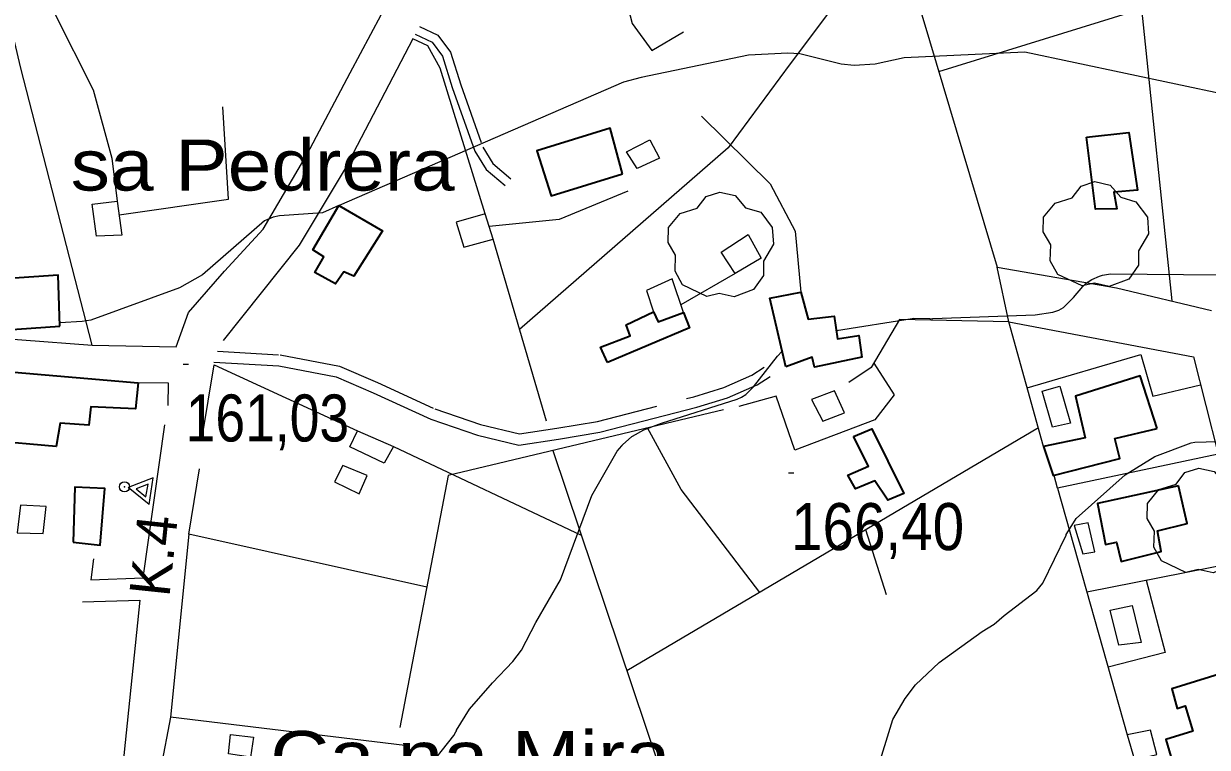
# Model space of a CAD drawing. Extents: x 480269 to 484877, y 4383588 to 4386804.
# Drawn here: x 481183 to 481403.4, y 4385293.4 to 4385428.1 of the extents above; entities that cross this region are included whole.
import ezdxf
from ezdxf.enums import TextEntityAlignment as Align

# ---------------------------------------------------------------- set-up
doc = ezdxf.new("R2010")
doc.units = 0
doc.header["$LTSCALE"] = 3.8
doc.header["$PDMODE"] = 32
doc.header["$PDSIZE"] = 1.9
doc.linetypes.add('MEDIUM_DASHED', pattern=[4.5, 3, -1.5])
for name, color, linetype, lineweight in [('21', 7, 'Continuous', 25), ('29', 7, 'Continuous', 13), ('38', 7, 'Continuous', 25), ('41', 7, 'Continuous', 13), ('47', 7, 'Continuous', 35), ('51', 7, 'Continuous', 13), ('7', 7, 'Continuous', 13), ('9', 7, 'Continuous', 13)]:
    doc.layers.add(name, color=color, linetype=linetype, lineweight=lineweight)
doc.layers.add('5', color=7, linetype='Continuous')

msp = doc.modelspace()

# ---------------------------------------------------------------- linework, layer by layer
at = {"layer": '21'}
for points in [[(481377.88, 4385353.76), (481374.54, 4385353.01), (481372.59, 4385359.75), (481375.89, 4385360.67)], [(481380.16, 4385329.43), (481382.42, 4385329.81), (481381.2, 4385335.22), (481378.6, 4385334.74)], [(481391.04, 4385312.94), (481386.91, 4385312.47), (481385.3, 4385318.98), (481389.36, 4385319.83)]]:
    msp.add_lwpolyline(points, close=True, dxfattribs=at)
at = {"layer": '29'}
for points in [[(481310.22, 4385377.38), (481305.68, 4385379.5), (481304.27, 4385382.04), (481304.37, 4385385.02), (481303, 4385387.43), (481303.04, 4385390.18), (481305.2, 4385392.78), (481308.39, 4385393.78), (481310.04, 4385395.97), (481312.61, 4385396.8), (481315.47, 4385396.15), (481317.42, 4385393.88), (481320.23, 4385393.06), (481322.36, 4385390.21), (481322.6, 4385387.08), (481320.72, 4385383.93), (481320.72, 4385381.25), (481318.9, 4385378.64), (481315.28, 4385377.3), (481312.51, 4385377.93)], [(481380.05, 4385379.31), (481375.51, 4385381.43), (481374.1, 4385383.97), (481374.2, 4385386.95), (481372.83, 4385389.36), (481372.87, 4385392.11), (481375.03, 4385394.71), (481378.22, 4385395.71), (481379.87, 4385397.9), (481382.44, 4385398.73), (481385.3, 4385398.08), (481387.25, 4385395.81), (481390.06, 4385394.99), (481392.19, 4385392.14), (481392.43, 4385389.01), (481390.55, 4385385.86), (481390.55, 4385383.18), (481388.73, 4385380.57), (481385.11, 4385379.23), (481382.34, 4385379.86)], [(481399.37, 4385326), (481394.83, 4385328.12), (481393.42, 4385330.66), (481393.52, 4385333.64), (481392.15, 4385336.05), (481392.19, 4385338.8), (481394.35, 4385341.4), (481397.54, 4385342.4), (481399.19, 4385344.59), (481401.76, 4385345.42), (481404.62, 4385344.77), (481406.57, 4385342.5), (481409.38, 4385341.68), (481411.51, 4385338.83), (481411.75, 4385335.7), (481409.87, 4385332.55), (481409.87, 4385329.87), (481408.05, 4385327.26), (481404.43, 4385325.92), (481401.66, 4385326.55)]]:
    msp.add_lwpolyline(points, close=True, dxfattribs=at)
at = {"layer": '38', "linetype": 'MEDIUM_DASHED'}
for points in [[(481256.73, 4385427.61), (481260.15, 4385425.99), (481262.46, 4385422.83), (481264.39, 4385416.78), (481268.47, 4385405.16), (481270.39, 4385402.09), (481273.74, 4385399.24)], [(481219.11, 4385367.17), (481230.76, 4385366.48), (481241.8, 4385364.36), (481248.89, 4385361.31), (481259.57, 4385356.44), (481268.08, 4385353.52), (481275.31, 4385351.78), (481282.26, 4385352.82), (481289.86, 4385354.08), (481307.8, 4385358.69), (481313.33, 4385360.42), (481318.6, 4385362.69), (481320.88, 4385364.17)]]:
    msp.add_lwpolyline(points, dxfattribs=at)
at = {"layer": '38'}
for points in [[(481255.9, 4385426.18), (481259.07, 4385424.68), (481260.97, 4385422.07), (481262.82, 4385416.26), (481266.98, 4385404.43), (481269.13, 4385401), (481272.68, 4385397.99)], [(481218.45, 4385365.15), (481230.51, 4385364.45), (481241.19, 4385362.39), (481248.06, 4385359.43), (481258.81, 4385354.54), (481267.51, 4385351.55), (481275.22, 4385349.69), (481282.58, 4385350.8), (481290.28, 4385352.08), (481308.36, 4385356.72), (481314.04, 4385358.5), (481319.56, 4385360.88), (481321.99, 4385362.45)]]:
    msp.add_lwpolyline(points, dxfattribs=at)
at = {"layer": '41'}
for p, q in [((481207.13, 4385343.61), (481202.46, 4385341.81)), ((481206.36, 4385338.66), (481202.46, 4385341.81)), ((481206.36, 4385338.66), (481207.13, 4385343.61))]:
    msp.add_line(p, q, dxfattribs=at)
msp.add_lwpolyline([(481203.96, 4385341.56), (481205.8, 4385340.05), (481206.19, 4385342.4)], close=True, dxfattribs=at)
msp.add_point((481201.8, 4385341.91), dxfattribs=at)
at = {"layer": '47'}
for points in [[(481294.52, 4385400.18), (481292.21, 4385408.7), (481278.57, 4385404.44), (481281.2, 4385396.08)], [(481380.89, 4385407.02), (481388.72, 4385407.87), (481390.38, 4385397.16), (481385.97, 4385396.77), (481386.52, 4385393.67), (481382.57, 4385393.58)], [(481241.71, 4385394.3), (481249.84, 4385389.56), (481244.49, 4385381.11), (481242.64, 4385381.94), (481241.06, 4385379.68), (481237.22, 4385381.84), (481238.89, 4385384.75), (481236.88, 4385386.04)], [(481189.78, 4385371.83), (481189.43, 4385381.29), (481168.55, 4385379.92), (481169.2, 4385370.38)], [(481324.89, 4385364.24), (481321.89, 4385377.06), (481327.71, 4385378.13), (481329.07, 4385373.1), (481333.92, 4385373.67), (481334.52, 4385369.45), (481338.49, 4385370.09), (481339.04, 4385366.07), (481330.25, 4385364.19), (481329.77, 4385366.07)], [(481291.7, 4385365.07), (481290.39, 4385367.92), (481295.91, 4385370.01), (481295.18, 4385372.08), (481300.27, 4385374.47), (481301.12, 4385372.66), (481305.86, 4385374.38), (481306.99, 4385371.5)], [(481204.32, 4385361.26), (481203.82, 4385356.45), (481195.53, 4385356.79), (481195.15, 4385353.4), (481189.8, 4385353.78), (481189.05, 4385349.42), (481176.39, 4385350.53), (481177.62, 4385363.6)], [(481394.04, 4385352.76), (481390.85, 4385362.56), (481378.81, 4385358.78), (481380.6, 4385351.05), (481372.87, 4385349.44), (481374.68, 4385344.01), (481387.06, 4385347.21), (481386.14, 4385350.92)], [(481337.48, 4385351.27), (481340.92, 4385352.7), (481346.84, 4385340.69), (481343.9, 4385339.44), (481341.44, 4385343.01), (481337.86, 4385341.53), (481336.47, 4385344.09), (481340.27, 4385345.77)], [(481192.24, 4385331.61), (481197.25, 4385331.09), (481198.12, 4385341.58), (481192.58, 4385341.87)], [(481397.99, 4385342.08), (481382.91, 4385338.83), (481384.39, 4385331.17), (481386.43, 4385331.65), (481387.3, 4385328.05), (481394.76, 4385329.86), (481394.06, 4385333.76), (481399.61, 4385335.09)], [(481417.41, 4385294.85), (481414.29, 4385305.44), (481409.84, 4385304.29), (481408.17, 4385307.83), (481396.78, 4385304.34), (481397.74, 4385300.68), (481399.21, 4385301.15), (481400.67, 4385296.45), (481395.64, 4385294.9), (481397.2, 4385289.59)]]:
    msp.add_lwpolyline(points, close=True, dxfattribs=at)
at = {"layer": '47', "lineweight": 13}
for points in [[(481297.22, 4385401.16), (481295.25, 4385404.27), (481299.61, 4385406.51), (481301.4, 4385403.07)], [(481201.32, 4385388.78), (481196.61, 4385388.58), (481195.8, 4385394.56), (481200.42, 4385395.07)], [(481270.42, 4385388), (481268.93, 4385392.72), (481263.52, 4385391.2), (481264.95, 4385386.52)], [(481320.28, 4385384.48), (481315.44, 4385381.66), (481312.86, 4385385.62), (481317.89, 4385388.89)], [(481331.79, 4385354.17), (481335.81, 4385355.72), (481333.97, 4385359.8), (481329.7, 4385358.2)], [(481251.89, 4385349.42), (481250.15, 4385346.33), (481243.74, 4385349.36), (481245.15, 4385352.35)], [(481245.51, 4385340.64), (481246.98, 4385344.05), (481242.44, 4385345.89), (481240.87, 4385342.83)], [(481186.67, 4385333.21), (481187.23, 4385338.26), (481182.47, 4385338.5), (481181.82, 4385333.38)], [(481225.26, 4385291.59), (481221.14, 4385292.24), (481221.5, 4385295.8), (481225.83, 4385295.35)], [(481393.96, 4385292.11), (481392.79, 4385296.62), (481388.43, 4385295.78), (481389.78, 4385291.08)]]:
    msp.add_lwpolyline(points, close=True, dxfattribs=at)
at = {"layer": '51'}
for p, q in [((481391.1, 4385430.92), (481396.74, 4385376.54)), ((481280.33, 4385354.17), (481270.42, 4385388)), ((481315.44, 4385381.66), (481305.38, 4385375.81)), ((481366.41, 4385372.62), (481364.24, 4385382.84)), ((481371.91, 4385352.93), (481295.3, 4385307.64)), ((481251.89, 4385349.42), (481286.82, 4385332.9)), ((481375.47, 4385341.67), (481388.43, 4385295.78)), ((481213.8, 4385333.13), (481210.37, 4385299.06)), ((481343.65, 4385321.82), (481339.77, 4385333.93)), ((481410.31, 4385328.14), (481380.94, 4385322.32))]:
    msp.add_line(p, q, dxfattribs=at)
for points in [[(481195.81, 4385368.29), (481211.41, 4385368.01), (481213.7, 4385374.36), (481220.4, 4385382.08), (481227.61, 4385389.86), (481235.77, 4385403.85), (481243.78, 4385418.97), (481249.59, 4385429.81), (481259.98, 4385442.89), (481268.12, 4385454), (481279.82, 4385465.98), (481284.94, 4385470.05), (481298.86, 4385479.3), (481313.75, 4385487.91), (481322.51, 4385493.76), (481327.1, 4385500.21), (481346.7, 4385530.71), (481346.05, 4385534.66)], [(481353.38, 4385419.22), (481415.82, 4385438.58), (481372.71, 4385497.59)], [(481143.33, 4385372.24), (481195.81, 4385368.29), (481182.48, 4385419.88), (481165.64, 4385491.59), (481143.92, 4385462.46), (481161.94, 4385405.45), (481168.55, 4385379.92)], [(481345.21, 4385446.68), (481325.69, 4385420.67), (481314.14, 4385405.05), (481275.34, 4385371.23)], [(481346.48, 4385442.32), (481364.24, 4385382.84), (481386.46, 4385378.97), (481404.15, 4385374.77)], [(481293.98, 4385437.02), (481296.3, 4385428.17), (481299.95, 4385423.16), (481305.82, 4385426.63)], [(481188.68, 4385430.23), (481195.97, 4385415.81), (481199.46, 4385403.11), (481200.42, 4385395.07)], [(481268.93, 4385392.72), (481260.55, 4385419.88), (481258.23, 4385423.99), (481255.45, 4385425.32), (481242.88, 4385401.18), (481234.29, 4385386.89), (481220.19, 4385369.13)], [(481200.78, 4385392.55), (481221.16, 4385395.45), (481220.11, 4385412.63)], [(481309.23, 4385410.92), (481322.01, 4385398.32), (481326.62, 4385389.53), (481327.71, 4385378.13)], [(481295.51, 4385396.93), (481282.7, 4385391.69), (481269.69, 4385390.35)], [(481305.86, 4385374.38), (481303.73, 4385380.61), (481298.96, 4385378.47), (481300.27, 4385374.47)], [(481366.41, 4385372.62), (481346.08, 4385373.07), (481340.81, 4385364.14), (481336.62, 4385361.34)], [(481372.87, 4385349.44), (481366.41, 4385372.62), (481400.77, 4385366.13), (481405.35, 4385348.02), (481375.47, 4385341.67), (481374.82, 4385344.05)], [(481369.84, 4385360.34), (481390.95, 4385366.58), (481393.22, 4385358.78), (481402.09, 4385360.9)], [(481216.24, 4385351.09), (481218.51, 4385364.64), (481245.15, 4385352.35)], [(481341.27, 4385364.91), (481345.09, 4385359.05), (481341.49, 4385354.37), (481326.57, 4385348.75), (481323.09, 4385358.81), (481316.18, 4385356.86)], [(481209.93, 4385357.09), (481209.99, 4385361.2), (481204.32, 4385361.26)], [(481313.27, 4385356.25), (481262.07, 4385344.03), (481253.02, 4385297.09)], [(481196.02, 4385328.52), (481195.54, 4385324.62), (481205.28, 4385324.98), (481209.28, 4385353.46)], [(481320.03, 4385322.26), (481305.41, 4385341.42), (481299.14, 4385352.88)], [(481281.52, 4385348.68), (481301.3, 4385289.77), (481321.94, 4385219.51), (481270.07, 4385210.4), (481189.73, 4385198.47), (481188.61, 4385199.49), (481187.1, 4385201.86), (481200.82, 4385248.49)], [(481258.07, 4385323.22), (481213.8, 4385333.13), (481215.77, 4385345.26)], [(481391.98, 4385324.52), (481395.51, 4385311.08), (481384.88, 4385308.36)], [(481194, 4385320.53), (481204.64, 4385320.82), (481200.65, 4385281.67), (481192.97, 4385253.04), (481178.06, 4385200.54), (481162.34, 4385200.24), (481155.32, 4385281.49), (481152.28, 4385322.92)], [(481253.99, 4385293.8), (481210.37, 4385299.06), (481208.58, 4385289.59)]]:
    msp.add_lwpolyline(points, dxfattribs=at)
at = {"layer": '7'}
for p, q in [((481212.69, 4385364.73), (481213.69, 4385364.73)), ((481325.38, 4385344.51), (481326.38, 4385344.51))]:
    msp.add_line(p, q, dxfattribs=at)
at = {"layer": '9'}
for points in [[(481462.31, 4385397.87), (481453.43, 4385399.87), (481416.25, 4385412.92), (481369.39, 4385422.85), (481346.95, 4385421.8), (481341.51, 4385420.58), (481337.59, 4385420.35), (481335.17, 4385420.57), (481327.51, 4385422.49), (481325.26, 4385422.67), (481317.92, 4385422.26), (481297.96, 4385418.13), (481294.68, 4385417.23), (481241.74, 4385394.28)], [(481241.68, 4385394.26), (481238.65, 4385392.94), (481230.65, 4385392.35), (481229.44, 4385392.1), (481227.84, 4385391.42), (481216.32, 4385381.41), (481212.05, 4385378.97), (481195.53, 4385372.93), (481193.93, 4385372.67), (481189.76, 4385372.43)], [(481375.69, 4385374.81), (481376.56, 4385375.31), (481378.45, 4385377.16), (481380.16, 4385379.18), (481380.55, 4385379.57), (481380.62, 4385379.66), (481380.71, 4385379.74), (481381.88, 4385380.51), (481383.26, 4385381.14), (481383.86, 4385381.33), (481385.34, 4385381.55), (481405.77, 4385381.37)], [(481334.3, 4385370.99), (481348.44, 4385373.28), (481348.65, 4385373.29), (481351.68, 4385373.25), (481352.08, 4385373.22), (481352.14, 4385373.22), (481352.29, 4385373.24), (481371.3, 4385373.93), (481374.62, 4385374.46), (481375.69, 4385374.81)], [(481257.69, 4385288.79), (481263.09, 4385295.64), (481263.5, 4385296.3), (481263.57, 4385296.49), (481263.58, 4385296.63), (481266.02, 4385300.51), (481270.31, 4385305.42), (481274.06, 4385309.4), (481275.67, 4385311.52), (481278.35, 4385316.68), (481282.94, 4385324.63), (481288.77, 4385340.32), (481293.49, 4385348.53), (481294.39, 4385349.56), (481294.41, 4385349.6), (481294.41, 4385349.62), (481294.42, 4385349.65), (481294.49, 4385349.74), (481296.25, 4385351.29), (481296.35, 4385351.35), (481298.49, 4385352.51), (481301.76, 4385353.77), (481315.87, 4385358.25), (481316.66, 4385358.61), (481317.43, 4385359.13), (481318.91, 4385360.55), (481323.32, 4385366.26), (481324.13, 4385367.13), (481324.2, 4385367.19)], [(481335.67, 4385269.01), (481344.83, 4385298.62), (481347.12, 4385302.51), (481349.04, 4385305.04), (481353.44, 4385309.23), (481361.46, 4385314.98), (481363.68, 4385316.36), (481365.56, 4385317.99), (481371.64, 4385322.61), (481372.76, 4385324), (481377.05, 4385332.94), (481377.06, 4385333.04), (481377.08, 4385333.07), (481377.2, 4385333.24), (481378.97, 4385336.02), (481388.07, 4385344.14), (481393.6, 4385347.56), (481400.34, 4385350.08), (481401, 4385350.25), (481407.37, 4385350.43)]]:
    msp.add_lwpolyline(points, dxfattribs=at)

# ---------------------------------------------------------------- texts
at = {"layer": '41'}
msp.add_text('K.4', height=7.5, rotation=84, dxfattribs=at).set_placement((481210.14, 4385321.26))
at = {"layer": '5', "width": 1.15}
msp.add_text('sa Pedrera', height=9.5, dxfattribs=at).set_placement((481191.78, 4385397.07))
at = {"layer": '5', "width": 1.2}
msp.add_text('Ca na Mira', height=9.5, dxfattribs=at).set_placement((481303.47, 4385286.97), align=Align.RIGHT)
at = {"layer": '7'}
for s, width, p in [('161,03', 0.85, (481213.19, 4385350.36)), ('166,40', 0.9, (481325.88, 4385330.14))]:
    msp.add_text(s, height=8.75, dxfattribs=dict(at, width=width)).set_placement(p)

doc.saveas('drawing.dxf')
